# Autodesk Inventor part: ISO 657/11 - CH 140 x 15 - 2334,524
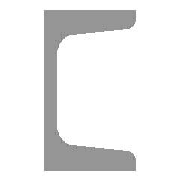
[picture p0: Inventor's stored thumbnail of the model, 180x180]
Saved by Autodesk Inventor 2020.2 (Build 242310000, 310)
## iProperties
Manager: www.cadconsulting.pl
Company: Fabian Stasiak CAD Consulting
Created: 2016-02
Part Number: ISO 657/11 - CH 140 x 15 - 2334,524
Material: Stal, miękka
Description: Ceowniki o nachylonych ramionach stalowe walcowane na gorąco
Document SubType Name: Modeling
Standard: ISO
Designer: F.Stasiak
Standard Revision: First edition 1980-09-01
Standards Organization: ISO
Language: pl-PL
Size Designation: CH 140 x 15
Categories: <MemberInstance><Categories><Category DisplayName="Kształtowniki konstrukcyjne" InternalName="089c4875-fa83-4c05-b084-43b9cc11f5ed" Mnemonic="GRDR"><CategoryPar
Stock Number: CH 140 x 15
Density: 7.85 g/cm^3
Appearance: Częściowo polerowana
Catalog Web Link: www.expertbooks.pl
_CCFamilyMember: 4
_CCFamilyDisplayName: ISO 657/11-1980(E) - Ceowniki o nachylonych ramionach stalowe walcowane na gorąco
_FrameMemberDoc: Frame Member File
_Version: 15.0.0
_GetPNFromCC: 1
G_L: 2334,524 mm
G_W: 60,000 mm
G_H: 140,000 mm
IsCustomPart: 1
Author: F.Stasiak
Subject: Zbiór ćwiczeń. Autodesk Inventor 2020. Kurs Professional
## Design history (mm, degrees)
node "Płaszczyzna początkowa"
node "Płaszczyzna końcowa"
sketch "Szkic"
  geometry: L1 (-1.68, 0)-(-1.68, 70); L2 (-1.68, 70)-(58.32, 70); L3 (58.32, 70)-(58.32, 67.853); L4 (54.29, 63.377)-(13.079, 59.046); L5 (5.02, 50.095)-(5.02, 0); L6 (5.02, 0)-(-1.68, 0); L7 (31.67, 70)-(31.67, 61); L8 (58.32, 63.801)-(58.32, 61); L9 (58.32, 61)-(31.67, 61); L10 (0, 15)-(0, -27); L11 (-5.539, 0)-(16.007, 0); L12 (-1.68, 0)-(-1.68, -70); L13 (-1.68, -70)-(58.32, -70); L14 (58.32, -70)-(58.32, -67.853); L15 (54.29, -63.377)-(13.079, -59.046); L16 (5.02, -50.095)-(5.02, 0); L17 (0, 98)-(0, -98) reference; L18 (-18.483, 0)-(72.123, 0) reference; A1 r 9 centre (14.02, 50.095) between (13.079, 59.046) and (5.02, 50.095); A2 r 9 centre (14.02, -50.095) between (5.02, -50.095) and (13.079, -59.046); A3 r 4.5 centre (53.82, 67.853) between (54.29, 63.377) and (58.32, 67.853); A4 r 4.5 centre (53.82, -67.853) between (58.32, -67.853) and (54.29, -63.377); 5 further points
  constraints: 32 end point, 12 point on line, 8 point on circle, 8 tangent, 6 symmetric about line, 4 centre point, 4 parallel, 3 collinear, 3 perpendicular, 2 equal radius, 5 other
  dimensions: "d0" = 6.7 distance between parallel lines of L1 L5 (= G_T); "d1" = 70 distance between parallel lines of L6 L2 (= 0.5 x G_H); "d2" = 60 distance between parallel lines of L3 L1 (= G_W); "d3" = 9 distance of L2.end L8.end (= G_T1); "d4" = 26.65 distance of L7.start L2.end (= G_C); "d5" = 2.80102 distance of L8.start L8.end (computed from G_NG, G_C); "d23" = 9 radius of A1 (= G_IR); "d24" = 4.5 radius of A3 (= G_ER); "d25" = 1.68 distance between parallel lines of L10 L12 (= ex)
extrude "Bryła" new body sketch "Szkic" stored distance "d6" = 2334.52351 (= G_L); taper "d7" = 0 deg
node "Driven Length"
  sketch "Sketch3"
    geometry: L1 (0, 0)-(10, 0) reference
    constraints: 2 end point, 1 horizontal
  workplane "Work Plane3"
  sketch "Sketch4"
    geometry: L1 (-2, 0)-(12, 0) reference; L2 (-2, 2334.524)-(12, 2334.524) reference
    dimensions: "d29" = 2334.52351 distance between parallel lines of L1 L2 (derived)
body "Solid1"
other parameters: "G_W" = 60 [user parameter; used in 1 equation term], "G_H" = 140 [user parameter; used in 1 equation term], "G_T" = 6.7 [user parameter; used in 1 equation term], "G_T1" = 9 [user parameter; used in 1 equation term], "G_NG" = 1.05104 [user parameter; used in 1 equation term], "G_ER" = 4.5 [user parameter; used in 1 equation term], "G_IR" = 9 [user parameter; used in 1 equation term], "G_C" = 26.65 [user parameter; used in 2 equation terms], "G_L" = 2334.52351 (= d29) [user parameter; used in 1 equation term], "ex" = 1.68 [user parameter; used in 1 equation term], "G_OFFSET_START" = 0 [user parameter; used in 1 equation term], "G_OFFSET_END" = 0 [user parameter; used in 1 equation term], "d26" = 0 (computed from G_OFFSET_START), "d27" = 2334.52351 (= G_OFFSET_END + B_L), "B_L" = 2334.52351 [user parameter; used in 1 equation term], "d28" = 90 deg
